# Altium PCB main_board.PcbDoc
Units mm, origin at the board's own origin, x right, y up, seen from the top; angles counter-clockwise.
Board outline 50.73 x 50.64 mm, 2 copper layers (Top Layer, Bottom Layer); 31 components, 36 nets, 158 pads, 116 vias.
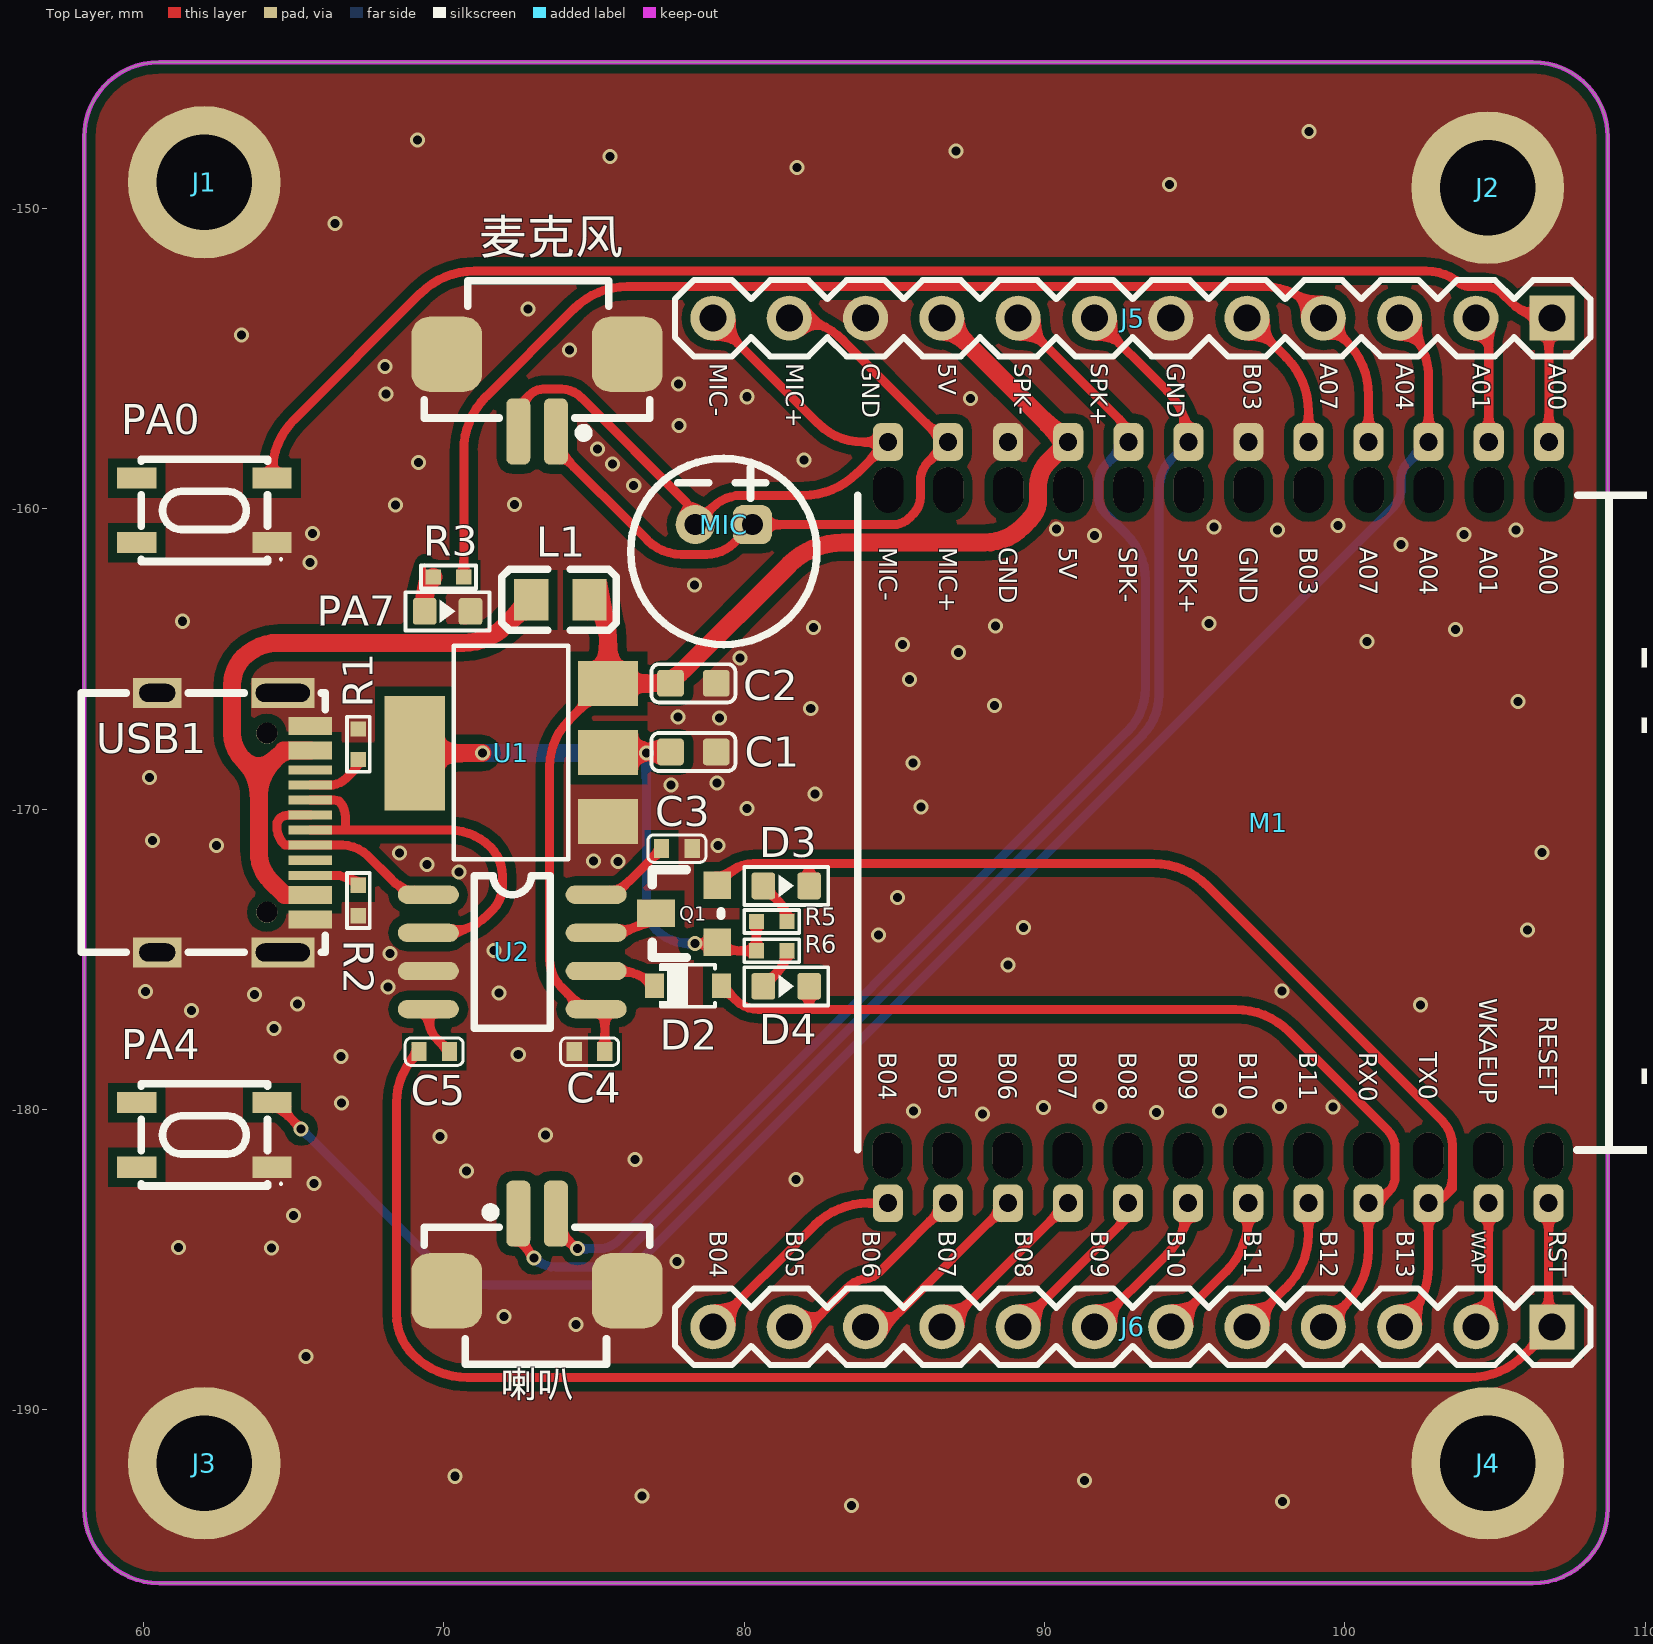
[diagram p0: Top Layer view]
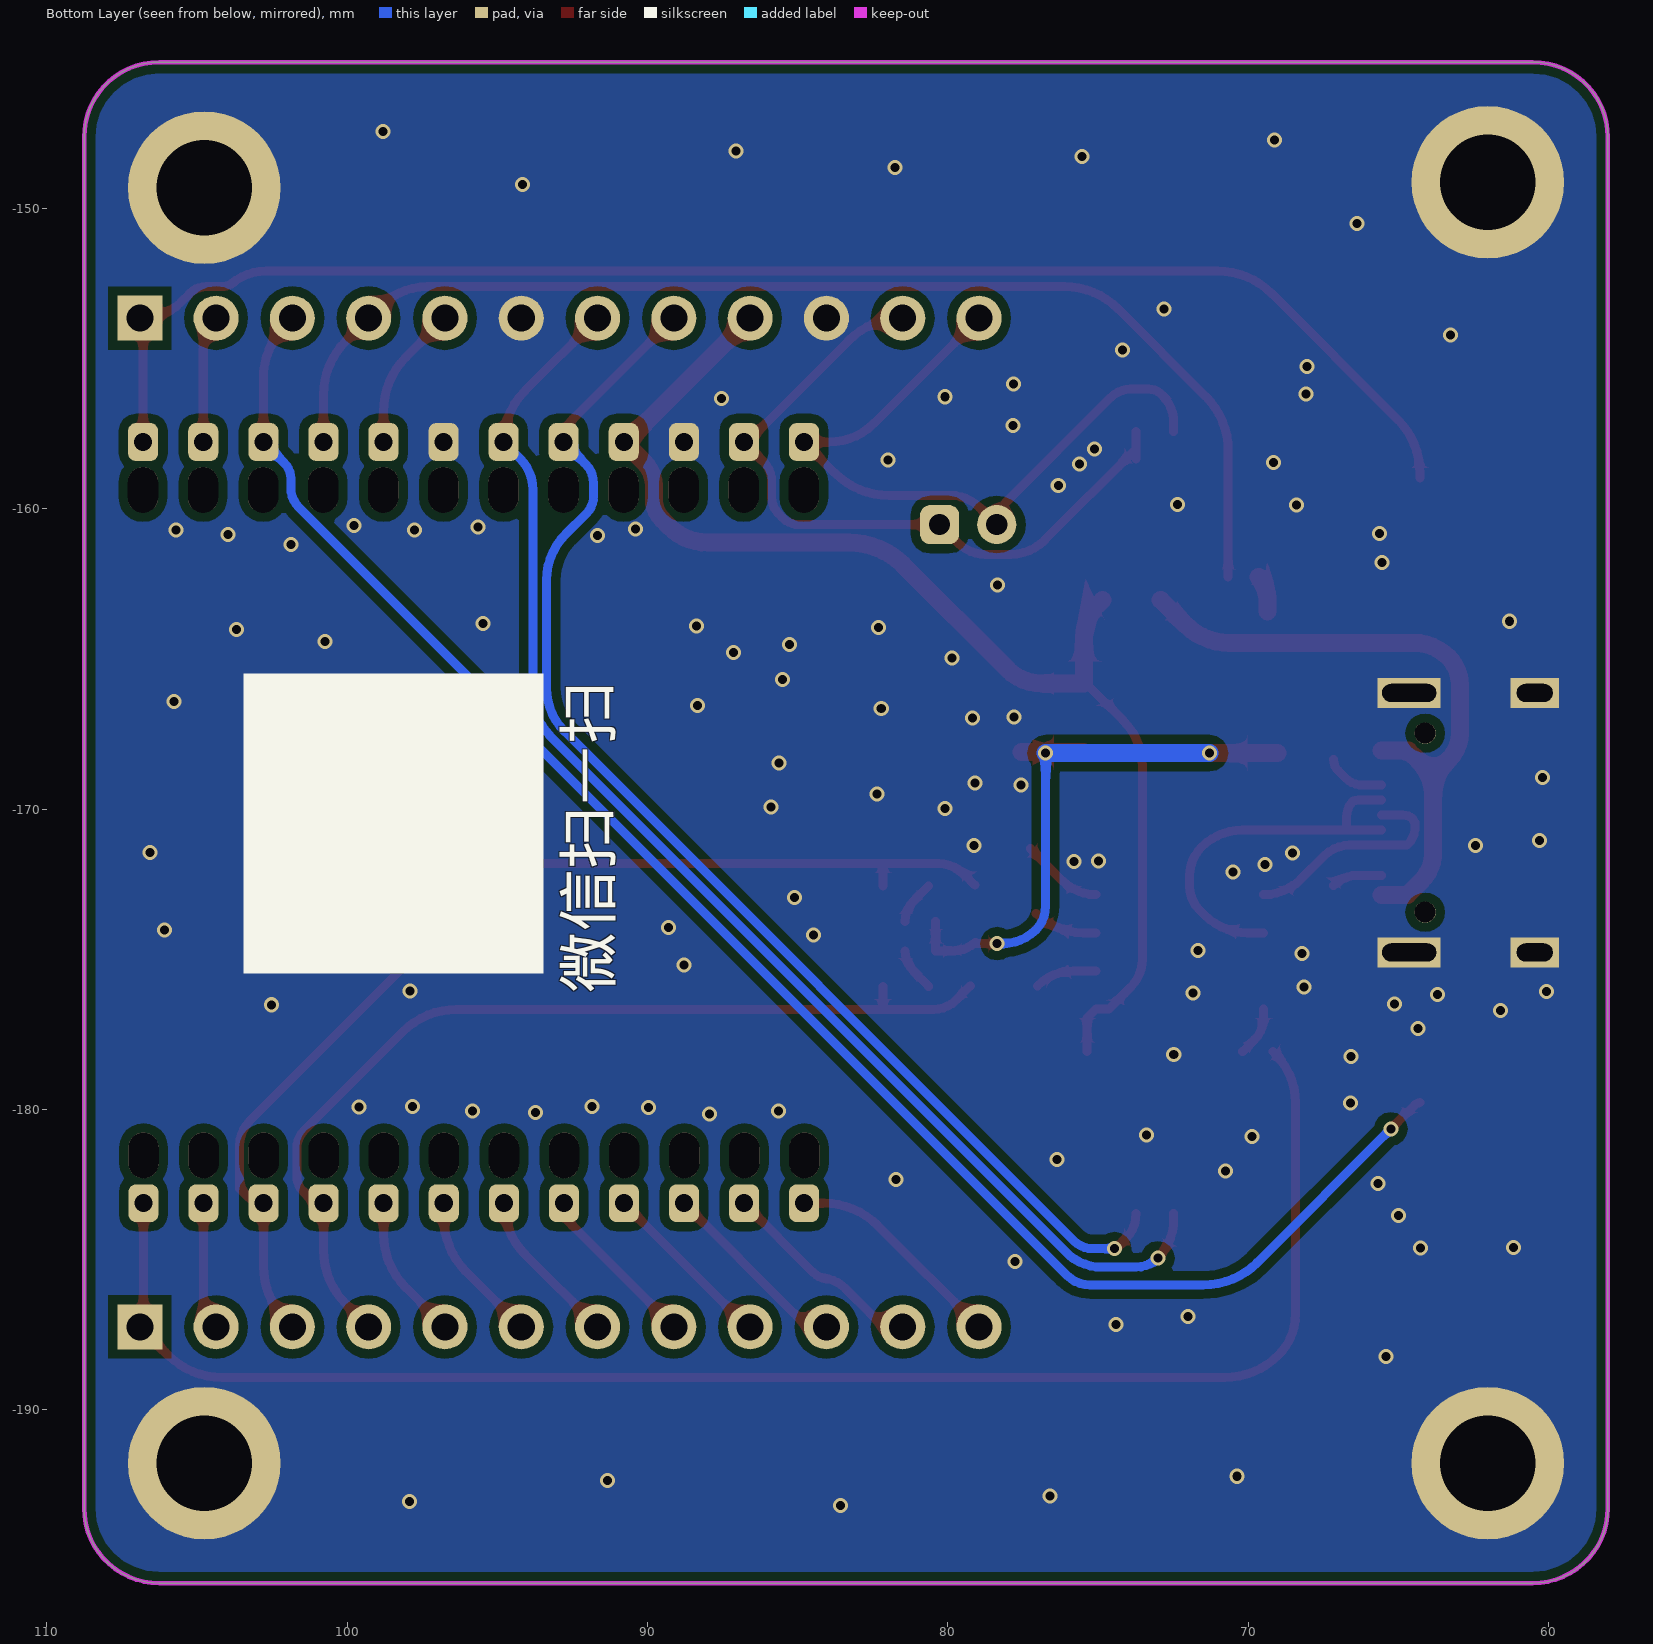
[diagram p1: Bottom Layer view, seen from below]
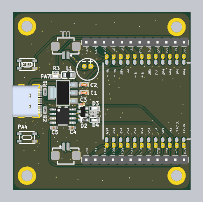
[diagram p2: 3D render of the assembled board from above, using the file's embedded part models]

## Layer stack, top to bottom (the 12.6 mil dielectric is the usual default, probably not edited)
Top Solder: solder mask 0.0102, Solder Resist, Dk 3.5
Top Layer: signal copper 0.0356
Dielectric 1: dielectric 0.32, FR-4, Dk 4.8
Bottom Layer: signal copper 0.0356
Bottom Solder: solder mask 0.0102, Solder Resist, Dk 3.5

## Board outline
58.024,-193.274 58.024,-147.616 58.024,-147.634 cw(c60.524,-147.634) 60.524,-145.134 106.254,-145.134 cw(c106.254,-147.634) 108.754,-147.634 108.754,-193.274 cw(c106.254,-193.274) 106.254,-195.774 60.524,-195.774 cw(c60.524,-193.274)

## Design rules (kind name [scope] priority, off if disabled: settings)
Clearance Clearance_freep_ad [HasPad('Free-6') Or HasPad('Free-7') Or HasPad('Free-8') or HasPad('Free-HOLE')] p1: gap=1
Clearance polygon [inpolygon] p2: gap=0.3
Clearance ic [HasFootprint('LQFP48_N') Or HasFootprint('HMC5883L')or HasFootprint('RP4')or HasFootprint('USBMICRO2') Or HasFootprint('JP2_SMD')] p3: gap=0.102
Clearance [All] p4: gap=0.15
ComponentClearance [All] p1: gap=0 collisioncheckmode=3 verticalgap=0.254 showdistances=FALSE
DiffPairsRouting [All] p1: maxlimit=0.254 minlimit=0.2 mostfreqgap=0.2 toplayer_minwidth=0.381 toplayer_maxwidth=0.381 toplayer_prefwidth=0.381 bottomlayer_minwidth=0.381 bottomlayer_maxwidth=0.381 bottomlayer_prefwidth=0.381 maxuncoupledlength=12.7
FabricationTestpoint [(IsPad And (OnTopLayer Or OnBottomLayer))] p1: side=3 testpointundercomponent=TRUE minsize=1.016 maxsize=2.54 preferedsize=1.524 minholesize=0 maxholesize=1.016 preferedholesize=0.813 testpointgrid=0.025 allowsidetop=TRUE allowsidebottom=TRUE usegrid=TRUE gridtolerance=0
HoleSize [All] p1: absolutevalues=TRUE maxlimit=5.08 minlimit=0.152 maxpercent=80.000 minpercent=20.000
MinimumSolderMaskSliver [All] p1: minsoldermaskwidth=0.025
PolygonConnect PolygonConnect_1 [isvia] p1: connectstyle=Direct reliefconductorwidth=0.254 reliefentries=4 polygonreliefangle="90 Angle" airgapwidth=0.254
PolygonConnect [All] p2: connectstyle=Direct reliefconductorwidth=0.254 reliefentries=4 polygonreliefangle="90 Angle" airgapwidth=0.254
RoutingVias [All] p1: holewidth=0.35 width=0.7 viastyle="Through Hole" minholewidth=0.3 minwidth=0.35 maxholewidth=10 maxwidth=10
ShortCircuit ShortCircuit_1 [OnLayer('Mechanical 13')] p1: allowed=TRUE
ShortCircuit [InNet('ANT1') vs InNet('GND')] p2: allowed=TRUE
SilkToSilkClearance [All] p1: silktosilkclearance=0
SilkToSolderMaskClearance SilkscreenOverComponentPads [IsPad] p1: minsilkscreentomaskgap=0.051 clearancetoexposedcopper=TRUE
SolderMaskExpansion [All] p1: expansion=0.051
Width Width_1 [InNet('VCC')] p1: maxlimit=25.4 minlimit=0.178 preferedwidth=0.635
Width [All] p2: maxlimit=10 minlimit=0.2 preferedwidth=0.254
22 further rules are at their usual default settings.

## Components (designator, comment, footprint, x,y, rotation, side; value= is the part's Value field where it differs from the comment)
C1 "C0603/10uF/6.3V" C0603 78.308,-168.1 r180 top
C2 "C0603/10uF/6.3V" C0603 78.308,-165.814 r180 top
C3 "100nF/16V" C0402 77.758,-171.318 r0 top
C4 "100nF/16V" C0402 74.853,-178.078 r0 top
C5 "4.7uF/6.3V" C0402 69.68,-178.078 r0 top
D2 "1N5819/SOD323" SOD-323 78.131,-175.885 r180 top
D3 "D0603_Red" D0603 81.398,-172.562 r0 top (schematic designator R4)
D4 "D0603_Green" D0603 81.398,-175.902 r0 top (schematic designator T1)
J1 "M3" "M3 125X200" 62.022,-149.134 r0 top
J2 "M3" "M3 125X200" 104.75,-149.315 r0 top
J3 "M3" "M3 125X200" 62.022,-191.778 r0 top
J4 "M3" "M3 125X200" 104.75,-191.778 r0 top
J5 "TXD043" PH_12PIN_DIP_2.54MM_180DEG 106.9,-153.66 r180 top
J6 "TXD043" PH_12PIN_DIP_2.54MM_180DEG 106.9,-187.24 r180 top
L1 "L-0805" L-0805 73.8,-163.031 r0 top
M1 "AI-02" WM-AI-Module 97.45,-170.454 r270 top locked
MIC "GMI6027P-2C30DB" MIC-TH_BD6.0-P1.90-D0.4-L 79.32,-161.43 r180 top locked
PA0 "Button" SW-SMD_4P-L4.2-W3.3-P2.15-LS5.1 62.027,-160.059 r180 top locked
PA4 "Button" SW-SMD_4P-L4.2-W3.3-P2.15-LS5.1 62.027,-180.852 r180 top locked
PA7 "D0603_Blue" D0603 70.125,-163.42 r0 top (schematic designator D1)
Q1 "NMOS/AO3402" SOT-23 78.079,-173.485 r90 top
R1 "5.1K" R0402 67.153,-167.846 r270 top
R2 "5.1K" R0402 67.153,-173.048 r90 top
R3 "1K" R0402 70.155,-162.277 r180 top
R5 "1K" R0402 80.915,-173.744 r0 top
R6 "1K" R0402 80.915,-174.72 r0 top
U1 "AMS1117/3.3V/SOT223" SOT223 72.247,-168.122 r90 top locked
U2 "CH340N" SOP8 72.277,-174.758 r0 top
USB1 "Type-C 母座 卧贴-直插" "TYPE-C 母座 卧贴-直插" 64.638,-174.776 r270 top locked
喇叭 "Header 2" CONN-SMD_2P-P1.25-HC-1.25-2PWT 73.103,-184.755 r0 top locked
麦克风 "Header 2" CONN-SMD_2P-P1.25-HC-1.25-2PWT 73.103,-156.145 r180 top

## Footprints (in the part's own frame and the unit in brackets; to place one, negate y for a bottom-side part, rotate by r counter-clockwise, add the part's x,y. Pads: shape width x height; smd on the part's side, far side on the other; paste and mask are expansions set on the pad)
C0402 [mil]
  rect 20x25 smd: 1(-20,0) 2(20,0)
  silkscreen extent -38,-18 38,18, body extent -20,-10 20,10, height 20
C0603 [mil]
  rrect25% 35x35 smd: 1(-30,0) 2(30,0)
  silkscreen extent -55,-25 55,25, body extent -39,-15 39,16, height 31
CONN-SMD_2P-P1.25-HC-1.25-2PWT [mm]
  rrect50% 0.8x2.2 smd paste+0 mask+0.05: 1(-0.625,1.285) 2(0.625,1.285)
  rrect50% 2.35x2.5 smd paste+0 mask+0.05: 3(-3.005,-1.285) 4(3.005,-1.285)
  silkscreen extent -3.75,-3.73 3.75,1.48
D0603 [mil]
  rrect25% 31x35 smd: 1(-30,0) 2(30,0)
  silkscreen extent -55,-25 55,25, body extent -32,-14 32,15, height 27
L-0805 [mm]
  rect 1.133x1.377 smd: 1(-0.89,-0.005) 2(1.043,-0.005)
  silkscreen extent -1.87,-1.02 1.94,1.01, body extent -1,-0.65 1,0.6, height 0.65
"M3 125X200" [mm] "M3螺丝孔，孔125Mil，焊盘200Mil"
  round 5.08 hole 3.175: 1(0,0)
MIC-TH_BD6.0-P1.90-D0.4-L [mm]
  rrect50% 1.3x1.3 hole 0.7: 1(-0.95,-0.9)
  round 1.3 hole 0.7: 2(0.95,-0.9)
  silkscreen extent -3.1,-3.1 3.1,3.1
PH_12PIN_DIP_2.54MM_180DEG [mm]
  rect 1.5x1.5 hole 0.9: 1(0,0)
  round 1.5 hole 0.9: 2(2.54,0) 3(5.08,0) 4(7.62,0) 5(10.16,0) 6(12.7,0) 7(15.24,0) 8(17.78,0) 9(20.32,0) 10(22.86,0) 11(25.4,0) 12(27.94,0)
  silkscreen extent -1.27,-1.27 29.21,1.27, body extent -1.27,-1.27 29.21,1.27, height 2.62
R0402 [mil]
  rect 20x20 smd: 1(-20,0) 2(20,0)
  silkscreen extent -36,-15 36,15, body extent -20,-10 20,10, height 20
SOD-323 [mm]
  rect 0.63x0.83 smd: 1(-1.115,0) 2(1.115,0)
  silkscreen extent -0.9,-0.7 0.96,0.7, body extent -1.35,-0.62 1.35,0.62, height 1.1
SOP8 [mil]
  oval 80x24 smd: 1(-110,75) 2(-110,25) 3(-110,-25) 4(-110,-75) 5(110,-75) 6(110,-25) 7(110,25) 8(110,75)
  silkscreen extent -50,-100 50,100, body extent -118,-96 118,96, height 69
SOT223 [mil]
  rect 59x79 smd: 1(-90.55,-126.77) 2(0,-126.77) 3(90.55,-126.77)
  rect 150x79 smd: 4(-0.67,126.77)
  silkscreen extent -140,-75 140,75, body extent -128,-140 128,140, height 65
SOT-23 [mil]
  rect 36x36 smd: 1(-37.5,-40) 2(37.5,-40)
  rect 36x50 smd: 3(0.5,40)
  silkscreen extent -58,-45 58,45, body extent -59,-49 59,49, height 41
SW-SMD_4P-L4.2-W3.3-P2.15-LS5.1 [mm]
  rect 1.3x0.701 smd mask+0.051: 1(-2.25,1.074) 2(2.25,1.074) 3(-2.25,-1.074) 4(2.25,-1.074)
  silkscreen extent -2.61,-1.7 2.1,1.7
"TYPE-C 母座 卧贴-直插" [mm]
  rect 1x2.1 hole 0.6 slot 1.8 at 90 deg: 13(-8.64,0) 14(0,0)
  rect 1x1.6 hole 0.6 slot 1.2 at 90 deg: 15(-8.64,-4.18) 16(0,-4.18)
  rect 0.6x1.45 smd: A1B12(-7.545,0.915) A4B9(-6.73,0.915) B1A12(-1.1,0.915) B4A9(-1.91,0.915)
  rect 0.3x1.45 smd: A5(-5.57,0.914) A6(-4.57,0.915) A7(-4.07,0.915) A8(-3.07,0.915) B5(-2.57,0.915) B6(-3.57,0.915) B7(-5.07,0.915) B8(-6.07,0.915)
  round 0.7 hole 0.7 unplated: ""(-7.3,-0.53) ""(-1.34,-0.53)
  silkscreen extent -8.64,-6.71 0,1.42, body extent -8.79,-6.79 0.15,1.11, height 3.2
WM-AI-Module [mm]
  rrect50% 1.26x1 hole 0.6: 1(-12.67,9.337) 2(-12.67,7.337) 3(-12.67,5.337) 4(-12.67,3.337) 5(-12.67,1.337) 6(-12.67,-0.663) 7(-12.67,-2.663) 8(-12.67,-4.663) 9(-12.67,-6.663) 10(-12.67,-8.663) 11(-12.67,-10.663) 12(-12.67,-12.663) 13(12.67,-12.669) 14(12.67,-10.669) 15(12.67,-8.669) 16(12.67,-6.669) 17(12.67,-4.669) 18(12.67,-2.669) 19(12.67,-0.669) 20(12.67,1.331) 21(12.67,3.331) 22(12.67,5.331) 23(12.67,7.331) 24(12.67,9.331)
  rect 0.5x0.5 on Top Overlay: 1(-3.25,12.676)
  oval 1.524x1 hole 1 slot 1.52 at 0 deg: ""(-11.08,5.344) ""(-11.08,7.344) ""(-11.08,9.344) ""(-11.08,-2.656) ""(-11.08,-0.656) ""(-11.08,1.344) ""(-11.08,3.344) ""(-11.08,-10.656) ""(-11.08,-8.656) ""(-11.08,-6.656) ""(-11.08,-4.656) ""(-11.08,-12.656) ""(11.08,5.324) ""(11.08,7.324) ""(11.08,9.324) ""(11.08,-2.676) ""(11.08,-0.676) ""(11.08,1.324) ""(11.08,3.324) ""(11.08,-10.676) ""(11.08,-8.676) ""(11.08,-6.676) ""(11.08,-4.676) ""(11.08,-12.676)
  silkscreen extent -10.9,-13.67 10.9,18.35

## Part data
C3 C4: library part C0402/100nF/16V
C5: library part C0402/4.7uF/6.3V
D4: library part D0603_Blue
J1 J2 J3 J4: "铜柱孔"
J5 J6: "4.3寸TFT 深圳市给力光电有限公司043202B0-40-N"
Q1: library part AO3402/SOT-23
R1 R2: library part R0402/5.1K
R3 R5 R6: library part R0402/1K
U2: library part CH330N/SOP8
喇叭 麦克风: "Header, 2-Pin"

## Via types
v1: diameter 0.5, hole 0.3, Top Layer to Bottom Layer, tented both sides, 116 vias

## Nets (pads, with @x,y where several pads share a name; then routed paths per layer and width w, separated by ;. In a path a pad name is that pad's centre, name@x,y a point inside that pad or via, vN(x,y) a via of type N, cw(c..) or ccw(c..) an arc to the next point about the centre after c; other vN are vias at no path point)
3V3: C1.2 Q1.1 R5.1 R6.1 U1.2 U1.4 | length 20.3
  Top Layer w0.3: v1(78.355,-174.481) 78.99,-174.481 ccw(c78.99,-174.332) Q1.1 ccw(c79.777,-173.755) 79.777,-174.72 R6.1 R5.1
  Top Layer w0.6: U1.4 v1(71.281,-168.139) ; U1.2 cw(c75.52,-168.175) 75.52,-168.1 C1.2
  Bottom Layer w0.3: v1(76.742,-168.139) 76.742,-173.232 ccw(c77.862,-173.232) 77.07,-174.024 ccw(c78.173,-172.921) 78.173,-174.481 v1(78.355,-174.481)
  Bottom Layer w0.6: v1(71.281,-168.139) v1(76.742,-168.139)
5V: C2.2 C4.2 J5.9 L1.2 M1.9 U1.3 U2.5 | length 41.9
  Top Layer w0.3: 74.163,-167.049 ccw(c75.714,-168.598) 73.522,-168.598 73.522,-174.999 ccw(c74.833,-174.999) 73.905,-175.925 74.643,-176.663 U2.5 75.361,-176.953 C4.2 ; 74.164,-167.048 75.39,-165.822 U1.3
  Top Layer w0.6: L1.2 75.022,-163.216 cw(c73.947,-164.29) 75.467,-164.29 U1.3 76.86,-165.822 ccw(c76.86,-164.185) 78.018,-165.342 81.486,-161.874 cw(c83.282,-163.67) 83.282,-161.13 88,-161.13 ccw(c88,-159.346) 89.261,-160.608 89.499,-160.37 ccw(c88.801,-159.672) 89.788,-159.672 89.788,-159.227 cw(c90.882,-159.227) 90.108,-158.453 M1.9@90.778,-157.784 ; J5.9 90.704,-157.784 M1.9@90.778,-157.784 ; M1.9 M1.9@90.778,-157.784
A1: J5.2 M1.2 | length 4.2
  Top Layer w0.3: J5.2 cw(c103.329,-154.691) 104.787,-154.691 M1.2
A4: J5.3 M1.3 PA4.3 | length 57.4
  Top Layer w0.3: PA4.3 cw(c64.277,-180.01) 64.442,-179.846 v1(65.248,-180.652) ; J5.3 102.043,-153.883 cw(c100.247,-155.679) 102.787,-155.679 M1.3
  Bottom Layer w0.3: v1(65.248,-180.652) 69.699,-185.103 ccw(c71.495,-183.307) 71.495,-185.847 75.259,-185.847 ccw(c75.259,-184.748) 76.035,-185.525 76.227,-185.334 101.596,-159.965 ; 101.596,-159.965 ccw(c100.932,-159.301) 101.871,-159.301 101.871,-158.992 cw(c102.576,-158.992) 102.077,-158.494 M1.3
A7: J5.4 M1.4 R3.1 | length 40.5
  Top Layer w0.3: R3.1 70.663,-158.067 cw(c73.203,-158.067) 71.407,-156.271 74.325,-153.353 cw(c76.121,-155.149) 76.121,-152.609 97.331,-152.609 cw(c97.331,-154.777) 98.863,-153.243 J5.4 100.043,-154.423 cw(c98.247,-156.219) 100.787,-156.219 M1.4
B3: J5.5 M1.5 | length 4.9
  Top Layer w0.3: J5.5 98.043,-154.963 cw(c96.247,-156.759) 98.787,-156.759 M1.5
B4: J6.12 M1.13 | length 7.4
  Top Layer w0.3: J6.12 82.332,-183.868 cw(c84.128,-185.664) 84.128,-183.124 M1.13
B5: J6.11 M1.14 | length 7.1
  Top Layer w0.3: J6.11 ccw(c81.5,-185.707) 82.584,-186.791 83.405,-185.97 cw(c84.309,-186.874) 83.96,-185.644 ; M1.14 84.473,-185.432 cw(c83.96,-184.919) 84.211,-185.599 ; 83.96,-185.644 ccw(c83.96,-184.919) 84.211,-185.599 ; 83.96,-185.644 cw(c84.309,-186.874) 84.211,-185.599
B6: J6.10 M1.15 | length 6.4
  Top Layer w0.3: J6.10 ccw(c84.04,-185.732) 85.106,-186.798 M1.15
B7: J6.9 M1.16 | length 5.9
  Top Layer w0.3: J6.9 ccw(c86.58,-187.036) 86.724,-187.18 M1.16
B8: J6.8 M1.17 | length 5.6
  Top Layer w0.3: J6.8 92.459,-183.901 ccw(c91.681,-183.124) M1.17
B9: J6.7 M1.18 | length 5.3
  Top Layer w0.3: J6.7 94.077,-184.823 ccw(c92.378,-183.124) M1.18
B10: J6.6 M1.19 | length 5.1
  Top Layer w0.3: J6.6 96.037,-185.403 ccw(c94.241,-183.607) 96.781,-183.607 M1.19
B11: J6.5 M1.20 | length 4.9
  Top Layer w0.3: J6.5 98.037,-185.943 ccw(c96.241,-184.147) 98.781,-184.147 M1.20
BOOT: J5.1 M1.1@106.787,-157.784 PA0.3 | length 50.7
  Top Layer w0.3: PA0.3 64.277,-158.83 cw(c66.817,-158.83) 65.021,-157.034 69.219,-152.836 cw(c71.015,-154.632) 71.015,-152.092 102.706,-152.092 cw(c102.706,-153.833) 103.71,-152.411 ; 105.242,-152.84 ccw(c104.686,-153.397) 104.686,-152.61 104.191,-152.61 cw(c104.191,-151.93) 103.841,-152.513 ; 105.243,-152.841 105.528,-153.126 ; 105.529,-153.127 ccw(c106.816,-151.839) 106.816,-153.66 J5.1 ccw(c107.172,-153.932) 106.787,-153.932 M1.1@106.787,-157.784 ; 103.71,-152.411 ccw(c104.191,-151.93) 103.841,-152.513 ; 103.71,-152.411 cw(c102.706,-153.833) 103.841,-152.513
D+: U2.1 USB1.A6 USB1.B6 | length 7.4
  Top Layer w0.3: 64.705,-171.205 cw(c65.347,-170.565) 64.44,-170.565 64.44,-170.503 cw(c64.553,-170.503) 64.473,-170.423 cw(c64.889,-170.592) 64.571,-170.275 cw(c64.843,-170.776) 64.843,-170.206 USB1.A6 ; 64.706,-171.206 USB1.B6 66.62,-171.206 cw(c66.62,-172.409) 67.47,-171.558 68.257,-172.345 ccw(c69.483,-171.12) U2.1
D-: U2.2 USB1.A7 USB1.B7 | length 12.7
  Top Layer w0.3: USB1.A7 66.719,-170.706 66.719,-170.256 ccw(c65.978,-170.256) 66.502,-169.732 ccw(c66.338,-170.245) 66.338,-169.706 USB1.B7 ; 66.775,-170.706 70.199,-170.706 cw(c70.199,-172.615) 71.549,-171.265 cw(c70.582,-172.231) 71.949,-172.231 71.949,-172.563 cw(c70.815,-172.563) 71.618,-173.364 ; U2.2 70.014,-174.123 ccw(c70.014,-172.083) 71.457,-173.525 71.617,-173.365
GND: C1.1 C2.1 C3.2 C4.1 J1.1 J2.1 J3.1 J4.1 J5.6 J5.10 M1.6 M1.10 PA0.1 PA4.1 PA7.2 R1.1 R2.1 U1.1 U2.3 USB1.13 USB1.14 USB1.15 USB1.16 USB1.A1B12 USB1.B1A12 喇叭.3 喇叭.4 麦克风.3 麦克风.4
  other v1: 83.566,-193.189 97.917,-193.05 76.599,-192.864 91.322,-192.353 70.376,-192.214 65.406,-188.22 74.397,-187.155 71.999,-186.896 77.763,-185.058 61.162,-184.601 64.257,-184.61 64.997,-183.533 65.683,-182.471 81.716,-182.328 70.754,-182.051 76.36,-181.675 69.877,-180.898 73.377,-180.848 87.94,-180.161 93.731,-180.102 85.636,-180.062 95.819,-180.062 89.969,-179.944 99.601,-179.925 91.84,-179.905 97.828,-179.905 66.585,-179.78 66.571,-178.233 72.477,-178.176 64.352,-177.305 61.605,-176.714 102.516,-176.517 65.132,-176.497 63.701,-176.179 71.832,-176.12 60.075,-176.076 97.907,-176.064 68.148,-175.928 88.787,-175.197 68.215,-174.808 71.665,-174.716 84.474,-174.193 106.081,-174.035 89.3,-173.937 85.104,-172.952 70.498,-172.096 69.432,-171.844 75.805,-171.74 74.98,-171.725 68.53,-171.471 106.554,-171.455 62.439,-171.209 79.122,-171.219 60.294,-171.042 80.095,-169.984 85.892,-169.938 82.363,-169.493 77.57,-169.2 79.101,-169.141 60.199,-168.945 85.616,-168.461 79.184,-166.967 77.797,-166.93 82.215,-166.649 88.334,-166.55 105.766,-166.413 85.506,-165.692 79.854,-164.971 87.133,-164.797 85.273,-164.518 100.739,-164.417 103.678,-164.029 82.301,-163.956 88.367,-163.907 95.472,-163.821 61.295,-163.749 78.339,-162.537 65.546,-161.788 101.862,-161.201 91.662,-160.9 103.958,-160.858 65.633,-160.835 97.752,-160.708 105.696,-160.708 90.392,-160.675 95.638,-160.608 99.765,-160.566 68.398,-159.878 72.35,-159.858 76.322,-159.231 75.615,-158.514 69.156,-158.463 81.995,-158.379 75.12,-158.008 77.825,-157.229 87.536,-156.336 80.088,-156.275 68.081,-156.177 77.81,-155.843 68.038,-155.267 74.18,-154.72 63.27,-154.223 72.795,-153.359 66.382,-150.507 94.155,-149.207 81.755,-148.65 75.531,-148.278 87.049,-148.092 69.122,-147.721 98.799,-147.442
MIC+: J5.11 M1.11 MIC.1 麦克风.1 | length 24.4
  Top Layer w0.3: 麦克风.1@73.728,-158.351 麦克风.1@73.728,-158.001 ; 麦克风.1 麦克风.1@73.728,-158.001 ; 76.782,-161.055 麦克风.1@73.728,-158.001 ; 76.783,-161.056 ccw(c77.907,-159.93) 77.907,-161.521 78.749,-161.521 ccw(c78.749,-160.241) 79.654,-161.146 79.917,-160.883 cw(c80.769,-161.735) 80.769,-160.53 84.962,-160.53 ccw(c84.962,-159.787) 85.487,-160.313 85.646,-160.153 ccw(c85.126,-159.633) 85.862,-159.633 85.862,-159.097 cw(c86.798,-159.097) 86.136,-158.435 M1.11 86.679,-157.784 83.299,-154.404 ccw(c81.503,-156.2) 81.503,-153.66 J5.11
  Bottom Layer w0.3: M1.11@86.679,-157.784 M1.11
MIC-: J5.12 M1.12 MIC.2 麦克风.2 | length 23.7
  Top Layer w0.3: 麦克风.2 72.478,-157.136 cw(c73.789,-157.136) 72.861,-156.21 ; 72.862,-156.209 cw(c73.309,-156.656) 73.309,-156.024 73.916,-156.024 cw(c73.916,-156.951) 74.571,-156.295 78.062,-159.786 ; 78.062,-159.786 cw(c77.318,-160.53) MIC.2 78.942,-159.959 ; 78.942,-159.958 cw(c79.908,-160.925) 79.908,-159.558 81.961,-159.558 ccw(c81.961,-157.018) 83.757,-158.814 M1.12 83.952,-157.784 cw(c83.952,-155.688) 82.47,-157.17 J5.12
NetC3_1: C3.1 U2.8 | length 2.7
  Top Layer w0.3: U2.8 ccw(c75.071,-171.298) 76.17,-172.398 C3.1
NetC5_2: C5.2 U2.4 | length 1.7
  Top Layer w0.3: U2.4 69.483,-176.948 ccw(c70.509,-176.948) 69.783,-177.674 C5.2
NetD1_1: PA7.1 R3.2 | length 1.2
  Top Layer w0.6: PA7.1 69.363,-162.962 cw(c70.333,-162.962) R3.2
NetD2_2: D2.2 U2.6 | length 2.1
  Top Layer w0.3: U2.6 75.828,-175.393 cw(c75.828,-177.073) D2.2
NetQ1_3: Q1.3 U2.7 | length 2.2
  Top Layer w0.3: U2.7 75.492,-174.123 ccw(c75.492,-171.901) Q1.3
NetR1_2: R1.2 USB1.A5 | length 2
  Top Layer w0.3: USB1.A5 66.176,-169.206 ccw(c66.176,-168.376) 66.763,-168.963 66.998,-168.728 ccw(c66.624,-168.354) R1.2
NetR2_2: R2.2 USB1.B5 | length 1.7
  Top Layer w0.3: USB1.B5 66.347,-172.206 cw(c66.347,-173.346) R2.2@67.153,-172.54
NetR4_1: D3.1 R5.2 | length 1.5
  Top Layer w0.3: D3.1 81.144,-173.07 cw(c80.471,-173.744) R5.2
NetR6_2: D4.1 R6.2 | length 1.5
  Top Layer w0.3: D4.1 81.144,-175.394 ccw(c80.471,-174.72) R6.2
RESET: C5.1 J6.1 M1.24 | length 53.3
  Top Layer w0.3: C5.1 69.098,-178.151 ccw(c70.736,-179.789) 68.42,-179.789 68.42,-186.815 ccw(c70.349,-186.815) 68.985,-188.179 ccw(c70.781,-186.383) 70.781,-188.923 104.165,-188.923 ccw(c104.165,-186.383) 105.961,-188.179 J6.1 106.781,-187.121 M1.24
RX: D3.2 J6.3 M1.22 Q1.2 | length 37
  Top Layer w0.3: Q1.2 79.453,-172.174 cw(c80.314,-173.035) 80.314,-171.817 82.159,-171.817 ; D3.2 82.16,-171.818 82.159,-171.817 ; J6.3 102.037,-187.023 ccw(c100.241,-185.227) 102.781,-185.227 M1.22 ccw(c102.781,-182.382) 103.305,-182.907 ; 82.159,-171.817 93.623,-171.817 cw(c93.623,-174.357) 95.419,-172.561 103.235,-180.377 cw(c102.416,-181.196) 103.574,-181.196 103.574,-182.258 ; 103.305,-182.907 ccw(c102.656,-182.258) 103.574,-182.258 ; 103.305,-182.907 103.574,-182.638 103.574,-182.258
SPK+: J5.7 M1.7 喇叭.1 | length 44.8
  Top Layer w0.3: 喇叭.1 72.478,-183.673 ccw(c74.284,-183.673) v1(73.007,-184.95) ; J5.7 94.083,-156.083 cw(c92.381,-157.784) M1.7
  Bottom Layer w0.3: v1(73.007,-184.95) ccw(c73.736,-184.221) 73.736,-185.252 74.869,-185.252 ccw(c74.869,-183.556) 75.94,-184.871 93.261,-167.55 ; 93.252,-167.542 ccw(c91.911,-166.2) 93.808,-166.2 93.808,-159.378 cw(c95.292,-159.378) 94.243,-158.329 M1.7
SPK-: J5.8 M1.8 喇叭.2 | length 43.1
  Top Layer w0.3: 喇叭.2 ccw(c74.919,-183.47) 74.077,-184.312 74.4,-184.635 v1(74.448,-184.635) ; J5.8 92.464,-157.004 ; 92.465,-157.005 cw(c91.685,-157.784) M1.8
  Bottom Layer w0.3: v1(74.448,-184.635) 75.172,-184.635 ccw(c75.172,-183.748) 75.799,-184.375 92.757,-167.418 ; 92.757,-167.417 ccw(c91.305,-165.966) 93.358,-165.966 93.358,-162.38 ccw(c91.205,-162.38) 92.727,-160.857 92.033,-160.163 cw(c92.611,-159.584) 91.793,-159.584 91.793,-159.149 cw(c92.688,-159.149) 92.055,-158.516 M1.8
TX: D2.1 D4.2 J6.4 M1.21 | length 32.4
  Top Layer w0.3: D2.1 79.72,-176.36 ; 79.721,-176.36 ccw(c80.475,-175.605) 80.475,-176.672 82.153,-176.672 ; D4.2 82.16,-176.665 82.153,-176.672 ; J6.4 100.037,-186.483 ccw(c98.241,-184.687) 100.781,-184.687 M1.21 ccw(c100.781,-182.447) 101.259,-182.926 101.472,-182.713 ccw(c100.992,-182.233) 101.671,-182.233 101.671,-181.315 ccw(c100.768,-181.315) 101.407,-180.677 98.146,-177.416 ccw(c96.35,-179.212) 96.35,-176.672 82.153,-176.672
USB_VBUS: L1.1 USB1.A4B9 USB1.B4A9 | length 22.1
  Top Layer w0.6: 63.332,-164.946 ccw(c64.249,-165.862) 62.953,-165.862 62.953,-167.491 ccw(c64.154,-167.491) 63.305,-168.34 63.84,-168.875 ; 63.333,-164.945 cw(c64.488,-166.101) 64.488,-164.467 70.632,-164.467 ccw(c70.632,-162.422) 72.078,-163.868 L1.1 ; 64.235,-172.399 cw(c65.19,-171.445) 63.84,-171.445 63.84,-168.875 ; 64.235,-172.4 64.702,-172.866 USB1.B4A9 ; 64.669,-168.046 USB1.A4B9@65.014,-168.046 ; USB1.A4B9 USB1.A4B9@65.014,-168.046 ; 63.84,-168.875 64.426,-168.29 cw(c65.014,-168.878) USB1.A4B9@65.014,-168.046
WAKEUP: J6.2 M1.23 | length 4.2
  Top Layer w0.3: J6.2 ccw(c103.345,-186.225) 104.781,-186.225 M1.23
pads on no net: M1. M1.1@110.126,-167.204 PA0.2 PA0.4 PA4.2 PA4.4 USB1. USB1.A8 USB1.B8
copper on no net: | length 1180
  Bottom Layer w0.254: 325.099,-265.576 -64.994,-265.576 -66.864,-263.706 -66.864,-65.971 -65.228,-64.335 324.632,-64.335 332.111,-71.814 332.111,-258.564

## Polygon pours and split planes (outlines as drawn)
GND on Bottom Layer "Top Layer-No Net" (solid, remove dead copper, pour order 16): 35.442,-124.31 121.376,-124.31 121.019,-124.31 121.019,-209.159 35.442,-209.159
GND on Top Layer "Top Layer-No Net" (solid, remove dead copper, pour order 14): 42.851,-131.951 128.785,-131.951 128.428,-131.951 128.428,-209.555 42.852,-209.555

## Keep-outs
Keep-Out Layer:
  lines w0.15: 58.024,-147.634 cw(c60.524,-147.634) 60.524,-145.134 106.254,-145.134 cw(c106.254,-147.634) 108.754,-147.634 108.754,-193.274 cw(c106.254,-193.274) 106.254,-195.774 60.524,-195.774 cw(c60.524,-193.274) 58.024,-193.274 58.024,-147.616

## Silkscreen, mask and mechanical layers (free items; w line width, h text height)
Top Overlay:
  text "MIC-" at 78.652,-155.157 h1 r270
  text "MIC+" at 81.192,-155.157 h1 r270
  text "GND" at 83.732,-155.157 h1 r270
  text "5V" at 86.272,-155.157 h1 r270
  text "SPK-" at 88.812,-155.157 h0.96 r270
  text "SPK+" at 91.352,-155.157 h0.96 r270
  text "GND" at 93.892,-155.157 h1 r270
  text "B03" at 96.432,-155.157 h1 r270
  text "A07" at 98.972,-155.157 h1 r270
  text "A04" at 101.512,-155.157 h1 r270
  text "A01" at 104.052,-155.157 h1 r270
  text "A00" at 106.592,-155.157 h1 r270
  text "B04" at 78.66,-184.043 h1 r270
  text "B05" at 81.2,-184.043 h1 r270
  text "B06" at 83.74,-184.043 h1 r270
  text "B07" at 86.28,-184.043 h1 r270
  text "B08" at 88.82,-184.043 h1 r270
  text "B09" at 91.36,-184.043 h1 r270
  text "B10" at 93.9,-184.043 h1 r270
  text "B11" at 96.44,-184.043 h1 r270
  text "B12" at 98.98,-184.043 h1 r270
  text "B13" at 101.52,-184.043 h1 r270
  text "WAP" at 104.06,-184.043 h0.8 r270
  text "RST" at 106.6,-184.043 h1 r270
Bottom Overlay:
  region: 103.454,-165.483 93.454,-165.483 93.454,-175.483 103.454,-175.483
  text "微信扫一扫" at 90.738,-176.169 h2.6 r270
